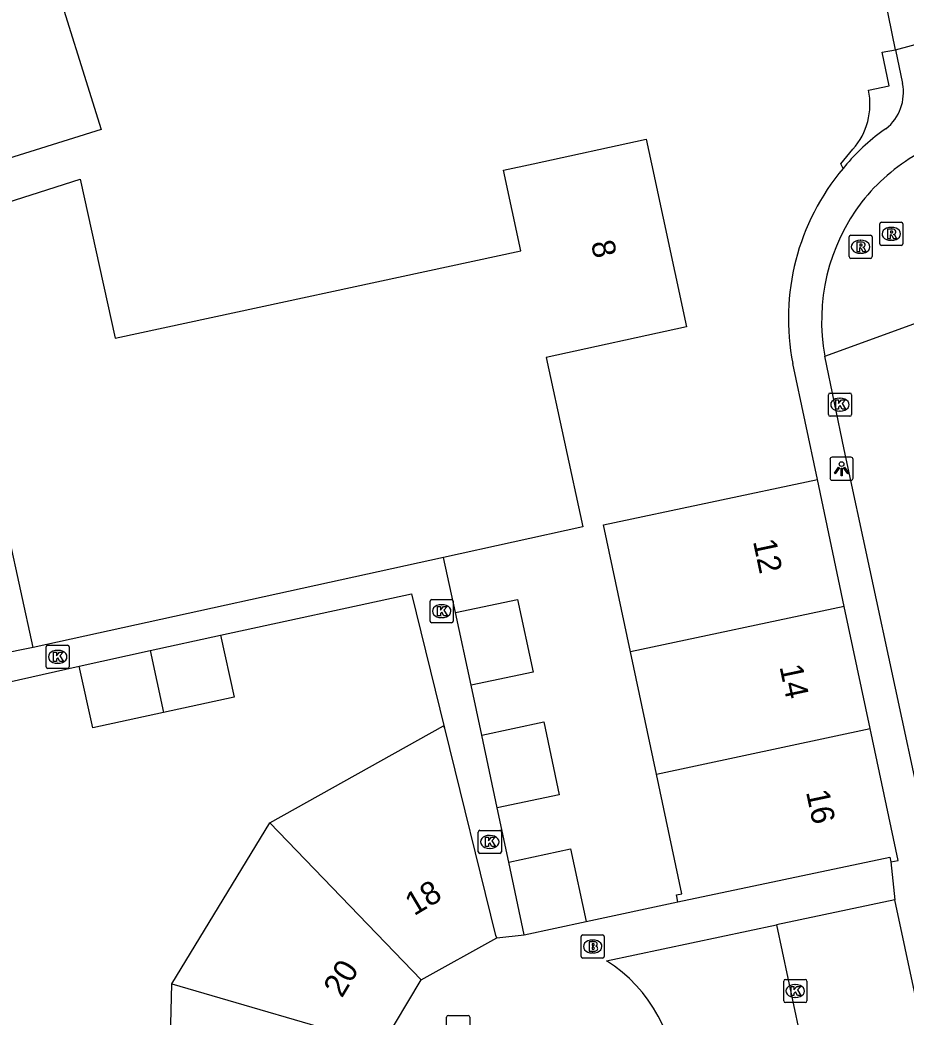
# Model space of a CAD drawing. Extents: x 162990 to 165007, y 383433 to 384336.
# Drawn here: x 163547.52 to 163585.79, y 383963.14 to 384006.22 of the extents above; entities that cross this region are included whole.
import ezdxf

# ---------------------------------------------------------------- set-up
doc = ezdxf.new("R2010")
doc.units = 0
for name, color, linetype in [('IMGEO_Brandkraan', 7, 'Continuous'), ('IMGEO_Kolk', 7, 'Continuous'), ('IMGEO_Lichtpunt', 7, 'Continuous'), ('IMGEO_Muur', 7, 'Continuous'), ('IMGEO_Pand', 7, 'Continuous'), ('IMGEO_Pand_nummerreeks', 7, 'Continuous'), ('IMGEO_Rijbaan_lokaal_open', 7, 'Continuous'), ('IMGEO_Rioolput', 7, 'Continuous'), ('IMGEO_Voetpad_open', 7, 'Continuous')]:
    doc.layers.add(name, color=color, linetype=linetype)

msp = doc.modelspace()

# ---------------------------------------------------------------- linework, layer by layer
at = {"layer": 'IMGEO_Brandkraan'}
for p, q in [((163571.756, 383965.762), (163571.756, 383966.614)), ((163571.831, 383966.688), (163572.683, 383966.688)), ((163572.757, 383966.614), (163572.757, 383965.762)), ((163572.244, 383966.468), (163572.269, 383966.468)), ((163572.683, 383965.688), (163571.831, 383965.688)), ((163572.267, 383965.908), (163572.242, 383965.908))]:
    msp.add_line(p, q, dxfattribs=at)
for points in [[(163571.756, 383965.762), (163571.756, 383966.614)], [(163571.831, 383966.688), (163572.683, 383966.688)], [(163572.757, 383966.614), (163572.757, 383965.762)], [(163572.104, 383966.388), (163572.104, 383965.988), (163572.317, 383965.988)], [(163572.335, 383966.388), (163572.104, 383966.388)], [(163572.283, 383966.307), (163572.229, 383966.307), (163572.229, 383966.231)], [(163572.229, 383966.231), (163572.282, 383966.231)], [(163572.291, 383966.155), (163572.229, 383966.155), (163572.229, 383966.074)], [(163572.683, 383965.688), (163571.831, 383965.688)], [(163572.229, 383966.074), (163572.291, 383966.074)]]:
    msp.add_lwpolyline(points, dxfattribs=at)
for centre, radius, start, end in [((163571.833, 383966.612), 0.0765, 91.552, 178.448), ((163571.833, 383966.612), 0.0765, 91.552, 178.448), ((163572.681, 383966.612), 0.0765, 1.552, 88.448), ((163572.681, 383966.612), 0.0765, 1.552, 88.448), ((163572.284, 383966.269), 0.0379, 267.8285, 90.9355), ((163572.292, 383966.114), 0.0404, 269.8759, 90.5077), ((163572.339, 383966.243), 0.145, 59.4692, 91.5367), ((163572.364, 383966.29), 0.0922, 285.5137, 58.1501), ((163572.369, 383966.098), 0.105, 301.3115, 78.989), ((163571.833, 383965.764), 0.0765, 181.552, 268.448), ((163571.833, 383965.764), 0.0765, 181.552, 268.448), ((163572.323, 383966.239), 0.251, 268.6676, 293.5347), ((163572.681, 383965.764), 0.0765, 271.552, 358.448), ((163572.681, 383965.764), 0.0765, 271.552, 358.448)]:
    msp.add_arc(centre, radius, start, end, dxfattribs=at)
for centre, major_axis, ratio, start_param, end_param in [((163572.243, 383966.188), (-0.387, 0.002), 0.722429, 4.712389, 7.853982), ((163572.268, 383966.188), (-0.39, 0.002), 0.717154, 1.570796, 4.712389)]:
    msp.add_ellipse(centre, major_axis=major_axis, ratio=ratio, start_param=start_param, end_param=end_param, dxfattribs=at)
at = {"layer": 'IMGEO_Kolk'}
for p, q in [((163582.436, 383989.173), (163582.436, 383990.025)), ((163582.511, 383990.099), (163583.363, 383990.099)), ((163582.924, 383989.879), (163582.949, 383989.879)), ((163583.437, 383990.025), (163583.437, 383989.173)), ((163583.363, 383989.099), (163582.511, 383989.099)), ((163582.947, 383989.319), (163582.922, 383989.319)), ((163565.31, 383981.175), (163566.162, 383981.175)), ((163565.235, 383980.249), (163565.235, 383981.101)), ((163565.723, 383980.955), (163565.748, 383980.955)), ((163566.236, 383981.101), (163566.236, 383980.249)), ((163565.746, 383980.395), (163565.721, 383980.395)), ((163566.162, 383980.175), (163565.31, 383980.175)), ((163548.651, 383978.276), (163548.651, 383979.128)), ((163548.726, 383979.202), (163549.578, 383979.202)), ((163549.652, 383979.128), (163549.652, 383978.276)), ((163549.139, 383978.982), (163549.164, 383978.982)), ((163549.578, 383978.202), (163548.726, 383978.202)), ((163549.162, 383978.422), (163549.137, 383978.422)), ((163567.314, 383970.28), (163567.314, 383971.132)), ((163567.389, 383971.206), (163568.241, 383971.206)), ((163567.802, 383970.986), (163567.827, 383970.986)), ((163568.315, 383971.132), (163568.315, 383970.28)), ((163567.825, 383970.426), (163567.8, 383970.426)), ((163568.241, 383970.206), (163567.389, 383970.206)), ((163580.506, 383963.84), (163580.506, 383964.692)), ((163580.581, 383964.766), (163581.433, 383964.766)), ((163580.994, 383964.546), (163581.019, 383964.546)), ((163581.507, 383964.692), (163581.507, 383963.84)), ((163581.017, 383963.986), (163580.992, 383963.986)), ((163581.433, 383963.766), (163580.581, 383963.766))]:
    msp.add_line(p, q, dxfattribs=at)
for points in [[(163582.436, 383989.173), (163582.436, 383990.025)], [(163582.511, 383990.099), (163583.363, 383990.099)], [(163582.757, 383989.799), (163582.88, 383989.799), (163582.88, 383989.648), (163583.01, 383989.799), (163583.174, 383989.799), (163583.028, 383989.648), (163583.181, 383989.399), (163583.029, 383989.399), (163582.944, 383989.563), (163582.88, 383989.496), (163582.88, 383989.399), (163582.757, 383989.399), (163582.757, 383989.799)], [(163583.437, 383990.025), (163583.437, 383989.173)], [(163583.363, 383989.099), (163582.511, 383989.099)], [(163565.31, 383981.175), (163566.162, 383981.175)], [(163565.235, 383980.249), (163565.235, 383981.101)], [(163565.556, 383980.875), (163565.679, 383980.875), (163565.679, 383980.724), (163565.809, 383980.875), (163565.973, 383980.875), (163565.827, 383980.724), (163565.98, 383980.475), (163565.828, 383980.475), (163565.743, 383980.639), (163565.679, 383980.572), (163565.679, 383980.475), (163565.556, 383980.475), (163565.556, 383980.875)], [(163566.236, 383981.101), (163566.236, 383980.249)], [(163566.162, 383980.175), (163565.31, 383980.175)], [(163548.651, 383978.276), (163548.651, 383979.128)], [(163548.726, 383979.202), (163549.578, 383979.202)], [(163549.652, 383979.128), (163549.652, 383978.276)], [(163548.972, 383978.902), (163549.095, 383978.902), (163549.095, 383978.751), (163549.225, 383978.902), (163549.389, 383978.902), (163549.243, 383978.751), (163549.396, 383978.502), (163549.244, 383978.502), (163549.159, 383978.666), (163549.095, 383978.599), (163549.095, 383978.502), (163548.972, 383978.502), (163548.972, 383978.902)], [(163549.578, 383978.202), (163548.726, 383978.202)], [(163567.314, 383970.28), (163567.314, 383971.132)], [(163567.389, 383971.206), (163568.241, 383971.206)], [(163567.635, 383970.906), (163567.758, 383970.906), (163567.758, 383970.755), (163567.888, 383970.906), (163568.052, 383970.906), (163567.906, 383970.755), (163568.059, 383970.506), (163567.907, 383970.506), (163567.822, 383970.67), (163567.758, 383970.603), (163567.758, 383970.506), (163567.635, 383970.506), (163567.635, 383970.906)], [(163568.315, 383971.132), (163568.315, 383970.28)], [(163568.241, 383970.206), (163567.389, 383970.206)], [(163580.506, 383963.84), (163580.506, 383964.692)], [(163580.581, 383964.766), (163581.433, 383964.766)], [(163580.827, 383964.466), (163580.95, 383964.466), (163580.95, 383964.315), (163581.08, 383964.466), (163581.244, 383964.466), (163581.098, 383964.315), (163581.251, 383964.066), (163581.099, 383964.066), (163581.014, 383964.23), (163580.95, 383964.163), (163580.95, 383964.066), (163580.827, 383964.066), (163580.827, 383964.466)], [(163581.507, 383964.692), (163581.507, 383963.84)], [(163581.433, 383963.766), (163580.581, 383963.766)]]:
    msp.add_lwpolyline(points, dxfattribs=at)
for centre, start, end in [((163582.513, 383990.023), 91.552, 178.448), ((163582.513, 383990.023), 91.552, 178.448), ((163583.361, 383990.023), 1.552, 88.448), ((163583.361, 383990.023), 1.552, 88.448), ((163582.513, 383989.175), 181.552, 268.448), ((163582.513, 383989.175), 181.552, 268.448), ((163583.361, 383989.175), 271.552, 358.448), ((163583.361, 383989.175), 271.552, 358.448), ((163565.312, 383981.099), 91.552, 178.448), ((163565.312, 383981.099), 91.552, 178.448), ((163566.16, 383981.099), 1.552, 88.448), ((163566.16, 383981.099), 1.552, 88.448), ((163565.312, 383980.251), 181.552, 268.448), ((163565.312, 383980.251), 181.552, 268.448), ((163566.16, 383980.251), 271.552, 358.448), ((163566.16, 383980.251), 271.552, 358.448), ((163548.728, 383979.126), 91.552, 178.448), ((163548.728, 383979.126), 91.552, 178.448), ((163549.576, 383979.126), 1.552, 88.448), ((163549.576, 383979.126), 1.552, 88.448), ((163548.728, 383978.278), 181.552, 268.448), ((163548.728, 383978.278), 181.552, 268.448), ((163549.576, 383978.278), 271.552, 358.448), ((163549.576, 383978.278), 271.552, 358.448), ((163567.391, 383971.13), 91.552, 178.448), ((163567.391, 383971.13), 91.552, 178.448), ((163568.239, 383971.13), 1.552, 88.448), ((163568.239, 383971.13), 1.552, 88.448), ((163567.391, 383970.282), 181.552, 268.448), ((163567.391, 383970.282), 181.552, 268.448), ((163568.239, 383970.282), 271.552, 358.448), ((163568.239, 383970.282), 271.552, 358.448), ((163580.583, 383964.69), 91.552, 178.448), ((163580.583, 383964.69), 91.552, 178.448), ((163581.431, 383964.69), 1.552, 88.448), ((163581.431, 383964.69), 1.552, 88.448), ((163580.583, 383963.842), 181.552, 268.448), ((163580.583, 383963.842), 181.552, 268.448), ((163581.431, 383963.842), 271.552, 358.448), ((163581.431, 383963.842), 271.552, 358.448)]:
    msp.add_arc(centre, 0.0765, start, end, dxfattribs=at)
for centre, major_axis, ratio, start_param, end_param in [((163582.923, 383989.599), (-0.387, 0.002), 0.722429, 4.712389, 7.853982), ((163582.948, 383989.599), (-0.39, 0.002), 0.717154, 1.570796, 4.712389), ((163565.722, 383980.675), (-0.387, 0.002), 0.722429, 4.712389, 7.853982), ((163565.747, 383980.675), (-0.39, 0.002), 0.717154, 1.570796, 4.712389), ((163549.138, 383978.702), (-0.387, 0.002), 0.722429, 4.712389, 7.853982), ((163549.163, 383978.702), (-0.39, 0.002), 0.717154, 1.570796, 4.712389), ((163567.801, 383970.706), (-0.387, 0.002), 0.722429, 4.712389, 7.853982), ((163567.826, 383970.706), (-0.39, 0.002), 0.717154, 1.570796, 4.712389), ((163580.993, 383964.266), (-0.387, 0.002), 0.722429, 4.712389, 7.853982), ((163581.018, 383964.266), (-0.39, 0.002), 0.717154, 1.570796, 4.712389)]:
    msp.add_ellipse(centre, major_axis=major_axis, ratio=ratio, start_param=start_param, end_param=end_param, dxfattribs=at)
at = {"layer": 'IMGEO_Lichtpunt'}
for p, q in [((163582.507, 383987.233), (163582.507, 383986.426)), ((163582.507, 383987.233), (163582.507, 383986.426)), ((163583.409, 383987.328), (163582.601, 383987.328)), ((163583.409, 383987.328), (163582.601, 383987.328)), ((163583.503, 383986.426), (163583.503, 383987.233)), ((163583.503, 383986.426), (163583.503, 383987.233)), ((163582.601, 383986.332), (163583.409, 383986.332)), ((163582.601, 383986.332), (163583.409, 383986.332))]:
    msp.add_line(p, q, dxfattribs=at)
for points in [[(163582.881, 383986.897), (163582.92, 383986.869), (163582.732, 383986.607), (163582.694, 383986.634), (163582.881, 383986.897)], [(163582.983, 383986.849), (163583.03, 383986.849), (163583.03, 383986.527), (163582.983, 383986.527), (163582.983, 383986.849)], [(163583.093, 383986.869), (163583.131, 383986.896), (163583.318, 383986.634), (163583.279, 383986.606), (163583.093, 383986.869)]]:
    msp.add_lwpolyline(points, dxfattribs=at)
msp.add_circle((163583.006, 383987.031), 0.0994, dxfattribs=at)
for centre, start, end in [((163582.601, 383987.233), 90, 180), ((163582.601, 383987.233), 90, 180), ((163583.409, 383987.233), 0, 90), ((163583.409, 383987.233), 0, 90), ((163582.601, 383986.426), 180, 270), ((163582.601, 383986.426), 180, 270), ((163583.409, 383986.426), 270, 0), ((163583.409, 383986.426), 270, 360)]:
    msp.add_arc(centre, 0.0946, start, end, dxfattribs=at)
at = {"layer": 'IMGEO_Muur'}
for points in [[(163584.17, 384003.182), (163585.058, 384003.374), (163584.759, 384004.825), (163585.331, 384004.933)], [(163585.331, 384004.933), (163585.641, 384003.474)], [(163583.07, 383999.8), (163582.973, 384000), (163583.5, 384000.63)], [(163583.235, 384000), (163583.07, 383999.8)], [(163581.964, 383986.357), (163580.9, 383991.373)], [(163571.972, 383967.266), (163575.94, 383968.112)]]:
    msp.add_lwpolyline(points, dxfattribs=at)
for centre, radius, start, end in [((163581.272, 384002.579), 2.96, 318.8236, 11.7556), ((163583.687, 384003.082), 1.993, 308.3632, 11.3556), ((163589.854, 383994.338), 8.711, 124.4743, 139.4589), ((163590.772, 383993.324), 10.063, 139.9424, 191.1771)]:
    msp.add_arc(centre, radius, start, end, dxfattribs=at)
at = {"layer": 'IMGEO_Pand'}
for points in [[(163548.762, 384008.736), (163551.033, 384001.488), (163546.285, 384000), (163538.949, 383997.701), (163538.229, 384000), (163529.392, 384028.198), (163534.824, 384029.9), (163535.572, 384027.298), (163535.829, 384027.373)], [(163548.093, 383979.112), (163547.032, 383983.998), (163544.112, 383997.429), (163550.127, 383999.345), (163551.637, 383992.463), (163569.15, 383996.241), (163568.41, 383999.73), (163569.685, 384000.008), (163574.57, 384001.072), (163574.801, 384000), (163576.314, 383992.963), (163570.249, 383991.631), (163571.831, 383984.312), (163565.814, 383982.994)], [(163573.886, 383978.922), (163572.719, 383984.4), (163581.964, 383986.357)], [(163583.123, 383980.88), (163581.964, 383986.357)], [(163565.814, 383982.994), (163548.093, 383979.112)], [(163566.334, 383980.616), (163569.015, 383981.185), (163569.682, 383978.04), (163567.002, 383977.472)], [(163583.123, 383980.88), (163573.886, 383978.922)], [(163584.241, 383975.599), (163583.123, 383980.88)], [(163567.002, 383977.472), (163566.334, 383980.616)], [(163553.139, 383978.969), (163556.188, 383979.633)], [(163556.188, 383979.633), (163556.77, 383976.959), (163553.722, 383976.295)], [(163550.083, 383978.303), (163553.139, 383978.969)], [(163553.139, 383978.969), (163553.722, 383976.295)], [(163575.011, 383973.64), (163573.886, 383978.922)], [(163553.722, 383976.295), (163550.665, 383975.629), (163550.083, 383978.303)], [(163558.311, 383971.535), (163565.807, 383975.727), (163565.861, 383975.623)], [(163565.861, 383975.623), (163568.065, 383966.656), (163568.114, 383966.568)], [(163567.464, 383975.318), (163570.144, 383975.887), (163570.811, 383972.742), (163568.131, 383972.174)], [(163575.011, 383973.64), (163584.241, 383975.599)], [(163585.131, 383969.84), (163585.446, 383969.907), (163584.241, 383975.599)], [(163568.131, 383972.174), (163567.464, 383975.318)], [(163575.94, 383968.112), (163575.873, 383968.421), (163576.113, 383968.465), (163575.011, 383973.64)], [(163554.084, 383964.573), (163558.311, 383971.535)], [(163564.855, 383964.746), (163558.311, 383971.535)], [(163568.63, 383969.832), (163571.303, 383970.403), (163571.972, 383967.266)], [(163575.94, 383968.112), (163585.088, 383970.052), (163585.131, 383969.84)], [(163569.299, 383966.695), (163568.63, 383969.832)], [(163569.299, 383966.695), (163571.972, 383967.266)], [(163564.855, 383964.746), (163568.114, 383966.568)], [(163553.874, 383956.462), (163554.084, 383964.573)], [(163554.084, 383964.573), (163563.161, 383961.93)], [(163563.161, 383961.93), (163564.855, 383964.746)]]:
    msp.add_lwpolyline(points, dxfattribs=at)
at = {"layer": 'IMGEO_Rijbaan_lokaal_open'}
for points in [[(163582.284, 383991.686), (163586.603, 383993.258)], [(163590.09, 383955.124), (163587.549, 383967.036), (163583.125, 383987.664), (163582.284, 383991.686)], [(163572.859, 383965.568), (163580.196, 383967.118)], [(163580.196, 383967.118), (163582.886, 383954.452), (163587.514, 383955.414), (163587.999, 383955.515)]]:
    msp.add_lwpolyline(points, dxfattribs=at)
for centre, radius, start, end in [((163590.634, 383992.959), 8.649, 120.3407, 141.312), ((163590.625, 383993.22), 8.481, 142.653, 190.4198), ((163569.34, 383960.044), 6.55, 359.6361, 57.5054)]:
    msp.add_arc(centre, radius, start, end, dxfattribs=at)
at = {"layer": 'IMGEO_Rioolput'}
for p, q in [((163584.654, 383996.551), (163584.654, 383997.403)), ((163584.729, 383997.477), (163585.581, 383997.477)), ((163585.142, 383997.257), (163585.167, 383997.257)), ((163585.655, 383997.403), (163585.655, 383996.551)), ((163583.328, 383995.992), (163583.328, 383996.844)), ((163583.403, 383996.918), (163584.255, 383996.918)), ((163583.816, 383996.698), (163583.841, 383996.698)), ((163584.329, 383996.844), (163584.329, 383995.992)), ((163585.165, 383996.697), (163585.14, 383996.697)), ((163585.581, 383996.477), (163584.729, 383996.477)), ((163584.255, 383995.918), (163583.403, 383995.918)), ((163583.839, 383996.138), (163583.814, 383996.138)), ((163565.948, 383962.287), (163565.948, 383963.139)), ((163566.023, 383963.213), (163566.875, 383963.213)), ((163566.949, 383963.139), (163566.949, 383962.287))]:
    msp.add_line(p, q, dxfattribs=at)
for points in [[(163584.654, 383996.551), (163584.654, 383997.403)], [(163584.729, 383997.477), (163585.581, 383997.477)], [(163585.243, 383997.175), (163584.991, 383997.177), (163584.991, 383996.777)], [(163585.169, 383997.096), (163585.115, 383997.096), (163585.115, 383997.015)], [(163585.655, 383997.403), (163585.655, 383996.551)], [(163583.328, 383995.992), (163583.328, 383996.844)], [(163583.403, 383996.918), (163584.255, 383996.918)], [(163584.329, 383996.844), (163584.329, 383995.992)], [(163584.991, 383996.777), (163585.115, 383996.777), (163585.115, 383996.939), (163585.126, 383996.939)], [(163585.115, 383997.015), (163585.167, 383997.015)], [(163585.173, 383996.91), (163585.244, 383996.777), (163585.384, 383996.777), (163585.319, 383996.903)], [(163583.917, 383996.616), (163583.665, 383996.618), (163583.665, 383996.218)], [(163583.665, 383996.218), (163583.789, 383996.218), (163583.789, 383996.38), (163583.8, 383996.38)], [(163583.843, 383996.537), (163583.789, 383996.537), (163583.789, 383996.456)], [(163583.789, 383996.456), (163583.841, 383996.456)], [(163583.847, 383996.351), (163583.918, 383996.218), (163584.058, 383996.218), (163583.993, 383996.344)], [(163585.581, 383996.477), (163584.729, 383996.477)], [(163584.255, 383995.918), (163583.403, 383995.918)], [(163565.948, 383962.287), (163565.948, 383963.139)], [(163566.023, 383963.213), (163566.875, 383963.213)], [(163566.949, 383963.139), (163566.949, 383962.287)]]:
    msp.add_lwpolyline(points, dxfattribs=at)
for centre, radius, start, end in [((163584.731, 383997.401), 0.0765, 91.552, 178.448), ((163584.731, 383997.401), 0.0765, 91.552, 178.448), ((163585.175, 383997), 0.0964, 77.0061, 93.1865), ((163585.242, 383997.065), 0.109, 350.3612, 89.416), ((163585.579, 383997.401), 0.0765, 1.552, 88.448), ((163585.579, 383997.401), 0.0765, 1.552, 88.448), ((163583.405, 383996.842), 0.0765, 91.552, 178.448), ((163583.405, 383996.842), 0.0765, 91.552, 178.448), ((163584.253, 383996.842), 0.0765, 1.552, 88.448), ((163584.253, 383996.842), 0.0765, 1.552, 88.448), ((163585.125, 383996.886), 0.0533, 26.0293, 88.6989), ((163585.151, 383997.204), 0.19, 274.7715, 282.9687), ((163585.189, 383997.057), 0.0378, 276.6634, 79.6772), ((163585.24, 383997.065), 0.112, 277.5842, 350.9817), ((163585.224, 383996.85), 0.108, 29.5134, 73.7905), ((163583.799, 383996.327), 0.0533, 26.0293, 88.6989), ((163583.825, 383996.645), 0.19, 274.7715, 282.9687), ((163583.849, 383996.441), 0.0964, 77.0061, 93.1865), ((163583.863, 383996.498), 0.0378, 276.6634, 79.6772), ((163583.916, 383996.506), 0.109, 350.3612, 89.416), ((163583.914, 383996.506), 0.112, 277.5842, 350.9817), ((163583.898, 383996.291), 0.108, 29.5134, 73.7905), ((163584.731, 383996.553), 0.0765, 181.552, 268.448), ((163584.731, 383996.553), 0.0765, 181.552, 268.448), ((163585.579, 383996.553), 0.0765, 271.552, 358.448), ((163585.579, 383996.553), 0.0765, 271.552, 358.448), ((163583.405, 383995.994), 0.0765, 181.552, 268.448), ((163583.405, 383995.994), 0.0765, 181.552, 268.448), ((163584.253, 383995.994), 0.0765, 271.552, 358.448), ((163584.253, 383995.994), 0.0765, 271.552, 358.448), ((163566.025, 383963.137), 0.0765, 91.552, 178.448), ((163566.025, 383963.137), 0.0765, 91.552, 178.448), ((163566.873, 383963.137), 0.0765, 1.552, 88.448), ((163566.873, 383963.137), 0.0765, 1.552, 88.448)]:
    msp.add_arc(centre, radius, start, end, dxfattribs=at)
for centre, major_axis, ratio, start_param, end_param in [((163585.141, 383996.977), (-0.387, 0.002), 0.722429, 4.712389, 7.853982), ((163585.166, 383996.977), (-0.39, 0.002), 0.717154, 1.570796, 4.712389), ((163583.815, 383996.418), (-0.387, 0.002), 0.722429, 4.712389, 7.853982), ((163583.84, 383996.418), (-0.39, 0.002), 0.717154, 1.570796, 4.712389)]:
    msp.add_ellipse(centre, major_axis=major_axis, ratio=ratio, start_param=start_param, end_param=end_param, dxfattribs=at)
at = {"layer": 'IMGEO_Voetpad_open'}
for points in [[(163585.331, 384004.933), (163584.083, 384011.089)], [(163585.331, 384004.933), (163587.727, 384005.569)], [(163581.964, 383986.357), (163580.9, 383991.373)], [(163566.334, 383980.616), (163565.814, 383982.994)], [(163556.188, 383979.633), (163564.437, 383981.417), (163565.861, 383975.623)], [(163548.093, 383979.112), (163545.161, 383978.514), (163545.575, 383969.06), (163546.971, 383969.08), (163546.429, 383977.483), (163550.083, 383978.303)], [(163567.464, 383975.318), (163567.002, 383977.472)], [(163568.63, 383969.832), (163568.131, 383972.174)], [(163585.131, 383969.84), (163585.307, 383968.197)], [(163571.972, 383967.266), (163575.94, 383968.112)], [(163585.307, 383968.197), (163580.196, 383967.118)], [(163587.999, 383955.515), (163587.048, 383960.048), (163585.307, 383968.197)], [(163568.114, 383966.568), (163569.299, 383966.695)]]:
    msp.add_lwpolyline(points, dxfattribs=at)
msp.add_arc((163590.772, 383993.324), 10.063, 139.9424, 191.1771, dxfattribs=at)

# ---------------------------------------------------------------- texts
at = {"layer": 'IMGEO_Pand_nummerreeks'}
for s, rotation, p in [('8', 282.1342, (163572.178, 383996.594)), ('12', 281.9515, (163579.176, 383983.694)), ('14', 281.9515, (163580.321, 383978.278)), ('16', 281.9515, (163581.467, 383972.865)), ('18', 30.7533, (163564.542, 383967.492)), ('20', 58.9705, (163561.424, 383963.932))]:
    msp.add_text(s, height=1, rotation=rotation, dxfattribs=at).set_placement(p)

doc.saveas('drawing.dxf')
